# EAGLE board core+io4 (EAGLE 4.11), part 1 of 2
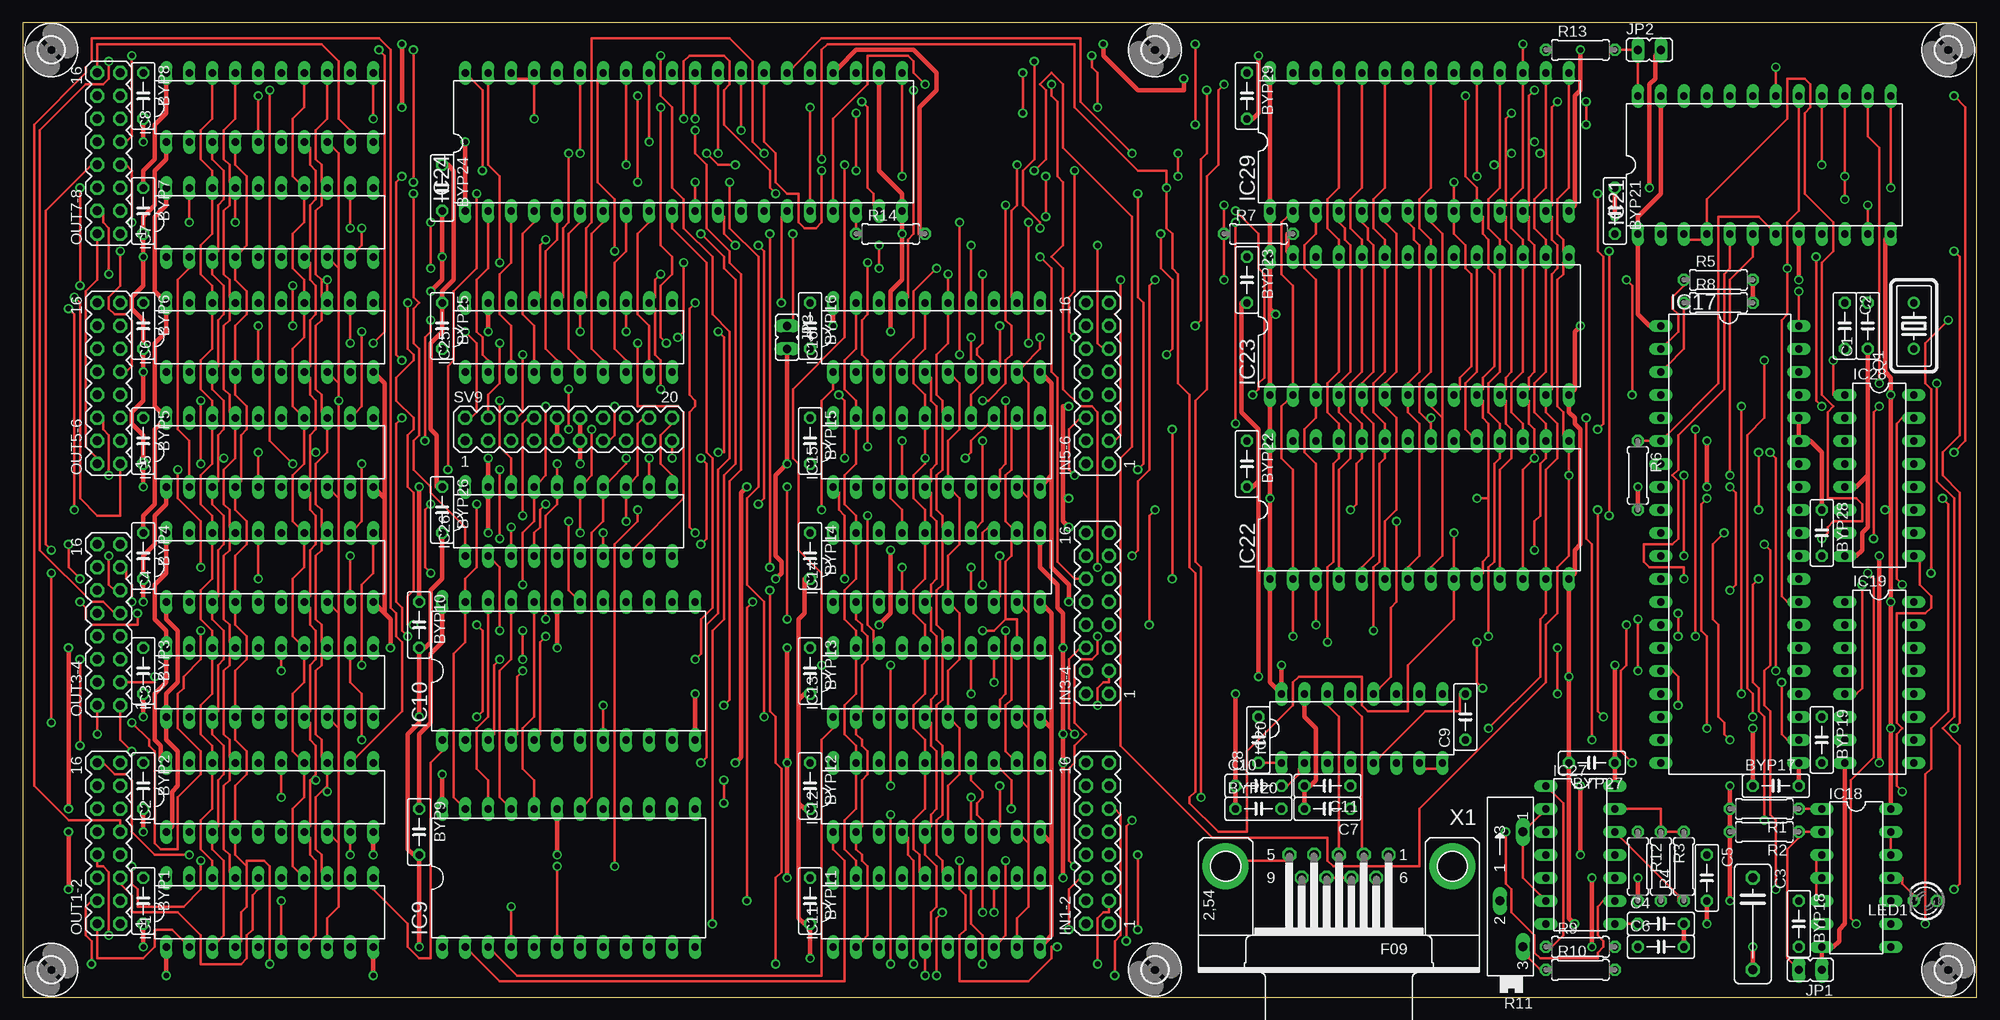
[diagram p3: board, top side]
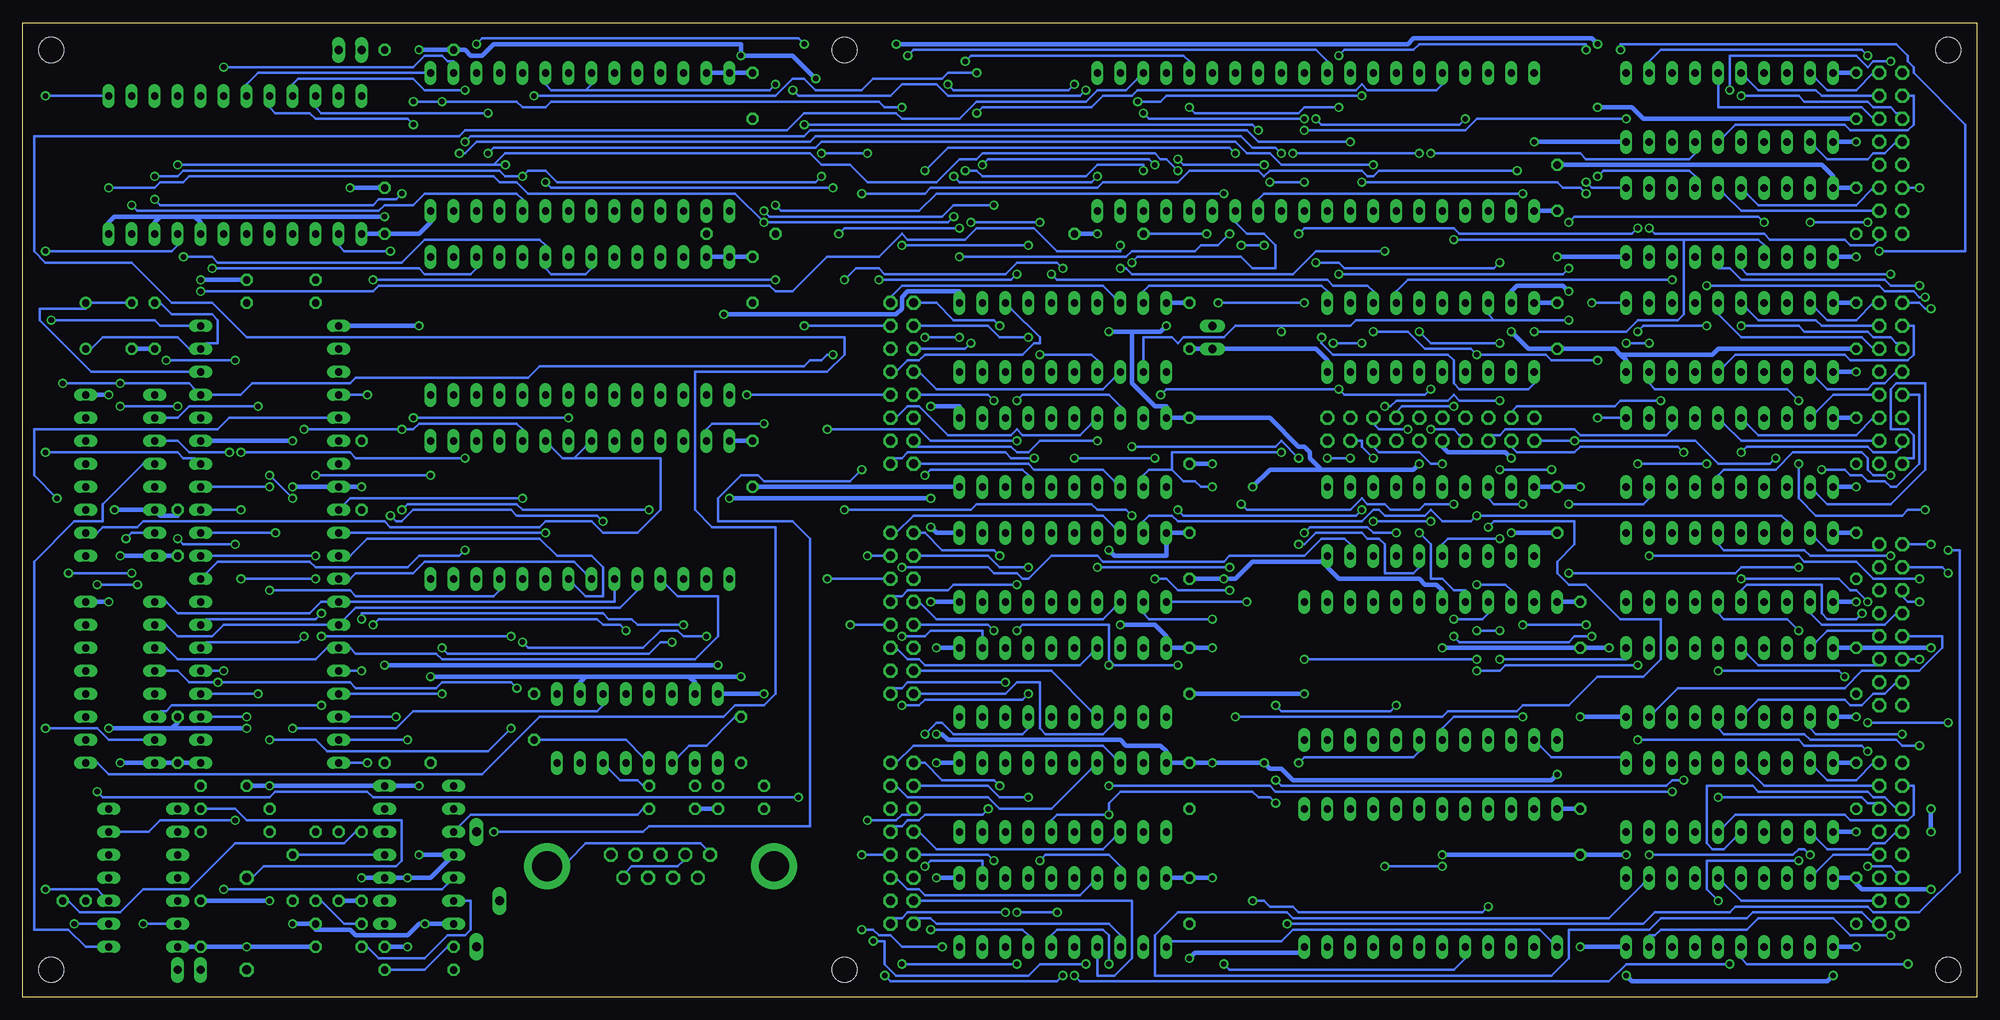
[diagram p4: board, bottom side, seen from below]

Size 215.88 x 107.62 mm. Coordinates in mm from the lower left corner, seen from the top.
Outline: 0,0 215.88,0 215.88,107.62 0,107.62 0,0
Copper layers (1*16): Top 0.035mm / dielectric 1.5mm / Bottom 0.035mm
Design rules "default": minimum track width 10mil, minimum drill 24mil, track to track 8mil, track to pad 8mil, pad to pad 8mil, via to via 8mil, smd to smd 8mil, copper to edge 40mil, drill to drill 8mil, minimum pad ring 10mil, minimum via ring 8mil, stop-mask expansion 4mil, vias tented up to drill 0mil, thermal gap 10mil
Net classes: 1 Power: width 0.508 mm, drill 0.254 mm, clearance 0.254 mm

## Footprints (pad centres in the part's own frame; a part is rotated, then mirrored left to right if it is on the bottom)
C050-025X075 = drill 0.813 octagon: 1 -2.54,0; 2 2.54,0
C102-043X133 = drill 1.016 octagon: 1 -5.08,0; 2 5.08,0
DIL20 = drill 0.813 long: 1 -11.43,-3.81; 2 -8.89,-3.81; 3 -6.35,-3.81; 4 -3.81,-3.81; 5 -1.27,-3.81; 6 1.27,-3.81; 7 3.81,-3.81; 8 6.35,-3.81; 9 8.89,-3.81; 10 11.43,-3.81; 11 11.43,3.81; 12 8.89,3.81; 13 6.35,3.81; 14 3.81,3.81; 15 1.27,3.81; 16 -1.27,3.81; 17 -3.81,3.81; 18 -6.35,3.81; 19 -8.89,3.81; 20 -11.43,3.81
DIL24-6 = drill 0.813 long: 1 -13.97,-7.62; 2 -11.43,-7.62; 3 -8.89,-7.62; 4 -6.35,-7.62; 5 -3.81,-7.62; 6 -1.27,-7.62; 7 1.27,-7.62; 8 3.81,-7.62; 9 6.35,-7.62; 10 8.89,-7.62; 11 11.43,-7.62; 12 13.97,-7.62; 13 13.97,7.62; 14 11.43,7.62; 15 8.89,7.62; 16 6.35,7.62; 17 3.81,7.62; 18 1.27,7.62; 19 -1.27,7.62; 20 -3.81,7.62; 21 -6.35,7.62; 22 -8.89,7.62; 23 -11.43,7.62; 24 -13.97,7.62
DIL40 = drill 0.813 long: 1 -24.13,-7.62; 2 -21.59,-7.62; 3 -19.05,-7.62; 4 -16.51,-7.62; 5 -13.97,-7.62; 6 -11.43,-7.62; 7 -8.89,-7.62; 8 -6.35,-7.62; 9 -3.81,-7.62; 10 -1.27,-7.62; 11 1.27,-7.62; 12 3.81,-7.62; 13 6.35,-7.62; 14 8.89,-7.62; 15 11.43,-7.62; 16 13.97,-7.62; 17 16.51,-7.62; 18 19.05,-7.62; 19 21.59,-7.62; 20 24.13,-7.62; 21 24.13,7.62; 22 21.59,7.62; 23 19.05,7.62; 24 16.51,7.62; 25 13.97,7.62; 26 11.43,7.62; 27 8.89,7.62; 28 6.35,7.62; 29 3.81,7.62; 30 1.27,7.62; 31 -1.27,7.62; 32 -3.81,7.62; 33 -6.35,7.62; 34 -8.89,7.62; 35 -11.43,7.62; 36 -13.97,7.62; 37 -16.51,7.62; 38 -19.05,7.62; 39 -21.59,7.62; 40 -24.13,7.62
DIL14 = drill 0.813 long: 1 -7.62,-3.81; 2 -5.08,-3.81; 3 -2.54,-3.81; 4 0,-3.81; 5 2.54,-3.81; 6 5.08,-3.81; 7 7.62,-3.81; 8 7.62,3.81; 9 5.08,3.81; 10 2.54,3.81; 11 0,3.81; 12 -2.54,3.81; 13 -5.08,3.81; 14 -7.62,3.81
DIL16 = drill 0.813 long: 1 -8.89,-3.81; 2 -6.35,-3.81; 3 -3.81,-3.81; 4 -1.27,-3.81; 5 1.27,-3.81; 6 3.81,-3.81; 7 6.35,-3.81; 8 8.89,-3.81; 9 8.89,3.81; 10 6.35,3.81; 11 3.81,3.81; 12 1.27,3.81; 13 -1.27,3.81; 14 -3.81,3.81; 15 -6.35,3.81; 16 -8.89,3.81
DIL24 = drill 0.813 long: 1 -13.97,-7.62; 2 -11.43,-7.62; 3 -8.89,-7.62; 4 -6.35,-7.62; 5 -3.81,-7.62; 6 -1.27,-7.62; 7 1.27,-7.62; 8 3.81,-7.62; 9 6.35,-7.62; 10 8.89,-7.62; 11 11.43,-7.62; 12 13.97,-7.62; 13 13.97,7.62; 14 11.43,7.62; 15 8.89,7.62; 16 6.35,7.62; 17 3.81,7.62; 18 1.27,7.62; 19 -1.27,7.62; 20 -3.81,7.62; 21 -6.35,7.62; 22 -8.89,7.62; 23 -11.43,7.62; 24 -13.97,7.62
DIL28 = drill 0.813 long: 1 -16.51,-7.62; 2 -13.97,-7.62; 3 -11.43,-7.62; 4 -8.89,-7.62; 5 -6.35,-7.62; 6 -3.81,-7.62; 7 -1.27,-7.62; 8 1.27,-7.62; 9 3.81,-7.62; 10 6.35,-7.62; 11 8.89,-7.62; 12 11.43,-7.62; 13 13.97,-7.62; 14 16.51,-7.62; 15 16.51,7.62; 16 13.97,7.62; 17 11.43,7.62; 18 8.89,7.62; 19 6.35,7.62; 20 3.81,7.62; 21 1.27,7.62; 22 -1.27,7.62; 23 -3.81,7.62; 24 -6.35,7.62; 25 -8.89,7.62; 26 -11.43,7.62; 27 -13.97,7.62; 28 -16.51,7.62
MA08-2 = drill 1.016 octagon: 1 -8.89,-1.27; 2 -8.89,1.27; 3 -6.35,-1.27; 4 -6.35,1.27; 5 -3.81,-1.27; 6 -3.81,1.27; 7 -1.27,-1.27; 8 -1.27,1.27; 9 1.27,-1.27; 10 1.27,1.27; 11 3.81,-1.27; 12 3.81,1.27; 13 6.35,-1.27; 14 6.35,1.27; 15 8.89,-1.27; 16 8.89,1.27
JP1 = drill 0.914 long: 1 0,-1.27; 2 0,1.27
LED3MM = drill 0.813 octagon: A -1.27,0; K 1.27,0
HC18U-V = drill 0.813 round: 1 -2.54,0; 2 2.54,0
0207/7 = drill 0.813 octagon: 1 -3.81,0; 2 3.81,0
SP19L = drill 1.016 long: A 5.715,-1.27; E -6.985,-1.27; S -1.905,1.27
MA10-2 = drill 1.016 octagon: 1 -11.43,-1.27; 2 -11.43,1.27; 3 -8.89,-1.27; 4 -8.89,1.27; 5 -6.35,-1.27; 6 -6.35,1.27; 7 -3.81,-1.27; 8 -3.81,1.27; 9 -1.27,-1.27; 10 -1.27,1.27; 11 1.27,-1.27; 12 1.27,1.27; 13 3.81,-1.27; 14 3.81,1.27; 15 6.35,-1.27; 16 6.35,1.27; 17 8.89,-1.27; 18 8.89,1.27; 19 11.43,-1.27; 20 11.43,1.27
2,8 = hole 2.8: 0,0
F09HP = drill 1.016 octagon: 1 -5.486,-1.27; 2 -2.743,-1.27; 3 0,-1.27; 4 2.743,-1.27; 5 5.486,-1.27; 6 -4.115,1.27; 7 -1.372,1.27; 8 1.372,1.27; 9 4.115,1.27 | drill 3.302 pad 5.08 round: G1 -12.522,0; G2 12.522,0

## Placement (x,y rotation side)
BYP1  .01uf  [C050-025X075]  13.33,10.63 270 top
BYP2  .01uf  [C050-025X075]  13.33,23.33 270 top
BYP3  .01uf  [C050-025X075]  13.33,36.03 270 top
BYP4  .01uf  [C050-025X075]  13.33,48.73 270 top
BYP5  .01uf  [C050-025X075]  13.33,61.43 270 top
BYP6  .01uf  [C050-025X075]  13.33,74.13 270 top
BYP7  .01uf  [C050-025X075]  13.33,86.83 270 top
BYP8  .01uf  [C050-025X075]  13.33,99.53 270 top
BYP9  .01uf  [C050-025X075]  43.81,18.25 270 top
BYP10  .01uf  [C050-025X075]  43.81,41.11 270 top
BYP11  .01uf  [C050-025X075]  86.99,10.63 270 top
BYP12  .01uf  [C050-025X075]  86.99,23.33 270 top
BYP13  .01uf  [C050-025X075]  86.99,36.03 270 top
BYP14  .01uf  [C050-025X075]  86.99,48.73 270 top
BYP15  .01uf  [C050-025X075]  86.99,61.43 270 top
BYP16  .01uf  [C050-025X075]  86.99,74.13 270 top
BYP17  .01uf  [C050-025X075]  193.67,23.33 0 top
BYP18  .01uf  [C050-025X075]  196.21,8.09 270 top
BYP19  .01uf  [C050-025X075]  198.75,28.41 270 top
BYP20  .01uf  [C050-025X075]  136.52,20.79 0 top
BYP21  .01uf  [C050-025X075]  175.89,86.83 270 top
BYP22  .01uf  [C050-025X075]  135.25,58.89 270 top
BYP23  .01uf  [C050-025X075]  135.25,79.21 270 top
BYP24  .01uf  [C050-025X075]  46.35,89.37 270 top
BYP25  .01uf  [C050-025X075]  46.35,74.13 270 top
BYP26  .01uf  [C050-025X075]  46.35,53.81 270 top
BYP27  .01uf  [C050-025X075]  173.35,25.87 180 top
BYP28  .01uf  [C050-025X075]  198.75,51.27 270 top
BYP29  .01uf  [C050-025X075]  135.25,99.53 270 top
C1  27pf  [C050-025X075]  203.83,74.13 90 top
C2  27pf  [C050-025X075]  201.29,74.13 270 top
C3  22uf  [C102-043X133]  191.13,8.09 270 top
C4  0.1uf  [C050-025X075]  180.97,8.09 0 top
C5  10uf  [C050-025X075]  186.05,13.17 270 top
C6  330pf  [C050-025X075]  180.97,5.55 0 top
C7  10uf  [C050-025X075]  144.14,20.79 180 top
C8  0.1uf  [C050-025X075]  136.52,28.41 90 top
C9  0.1uf  [C050-025X075]  159.38,30.95 90 top
C10  0.1uf  [C050-025X075]  136.52,23.33 0 top
C11  0.1uf  [C050-025X075]  144.14,23.33 180 top
IC1  74LS374N  [DIL20]  27.3,9.36 0 top
IC2  74LS374N  [DIL20]  27.3,22.06 0 top
IC3  74LS374N  [DIL20]  27.3,34.76 0 top
IC4  74LS374N  [DIL20]  27.3,47.46 0 top
IC5  74LS374N  [DIL20]  27.3,60.16 0 top
IC6  74LS374N  [DIL20]  27.3,72.86 0 top
IC7  74LS374N  [DIL20]  27.3,85.56 0 top
IC8  74LS374N  [DIL20]  27.3,98.26 0 top
IC9  74154N  [DIL24-6]  60.32,13.17 0 top
IC10  74154N  [DIL24-6]  60.32,36.03 0 top
IC11  74LS373N  [DIL20]  100.96,9.36 0 top
IC12  74LS373N  [DIL20]  100.96,22.06 0 top
IC13  74LS373N  [DIL20]  100.96,34.76 0 top
IC14  74LS373N  [DIL20]  100.96,47.46 0 top
IC15  74LS373N  [DIL20]  100.96,60.16 0 top
IC16  74LS373N  [DIL20]  100.96,72.86 0 top
IC17  [DIL40]  188.59,50 270 top
IC18  74LS00N  [DIL14]  202.56,13.17 270 top
IC19  74LS138N  [DIL16]  205.1,34.76 270 top
IC20  MAX232  [DIL16]  147.95,29.68 0 top
IC21  [DIL24]  192.4,91.91 0 top
IC22  5565  [DIL28]  154.3,53.81 0 top
IC23  2764  [DIL28]  154.3,74.13 0 top
IC24  [DIL40]  73.02,94.45 0 top
IC25  74LS245N  [DIL20]  60.32,72.86 0 top
IC26  74LS245N  [DIL20]  60.32,52.54 0 top
IC27  LM556N  [DIL14]  172.08,15.71 270 top
IC28  74LS138N  [DIL16]  205.1,57.62 270 top
IC29  2764  [DIL28]  154.3,94.45 0 top
IN1-2  [MA08-2]  118.74,16.98 90 top
IN3-4  [MA08-2]  118.74,42.38 90 top
IN5-6  [MA08-2]  118.74,67.78 90 top
JP1  RESET  [JP1]  197.48,3.01 90 top
JP2  DEBUG  [JP1]  179.7,104.61 270 top
JP3  CB1  [JP1]  84.45,72.86 180 top
LED1  [LED3MM]  210.18,10.63 180 top
OUT1-2  [MA08-2]  9.52,16.98 90 top
OUT3-4  [MA08-2]  9.52,41.11 90 top
OUT5-6  [MA08-2]  9.52,67.78 90 top
OUT7-8  [MA08-2]  9.52,93.18 90 top
Q1  4Mhz  [HC18U-V]  208.91,74.13 90 top
R1  10K  [0207/7]  192.4,20.79 180 top
R2  10K  [0207/7]  192.4,18.25 180 top
R3  100K  [0207/7]  180.97,14.44 270 top
R4  100K  [0207/7]  183.51,14.44 90 top
R5  3.3K  [0207/7]  187.32,79.21 0 top
R6  3.3K  [0207/7]  178.43,57.62 270 top
R7  3.3K  [0207/7]  136.52,84.29 0 top
R8  3.3K  [0207/7]  187.32,76.67 0 top
R9  1.8K  [0207/7]  172.08,5.55 0 top
R10  10K  [0207/7]  172.08,3.01 0 top
R11  10K  [SP19L]  164.46,12.54 90 top
R12  270  [0207/7]  178.43,14.44 270 top
R13  1K  [0207/7]  172.08,104.61 0 top
R14  3.3K  [0207/7]  95.88,84.29 0 top
SV9  [MA10-2]  60.32,62.7 0 top
U$1  [2,8]  125.09,3.01 0 top
U$2  [2,8]  125.09,104.61 0 top
U$3  [2,8]  3.17,104.61 0 top
U$4  [2,8]  3.17,3.01 0 top
U$5  [2,8]  212.72,104.61 0 top
U$6  [2,8]  212.72,3.01 0 top
X1  [F09HP]  145.41,14.44 180 top

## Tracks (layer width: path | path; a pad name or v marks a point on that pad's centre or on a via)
A00  (via drill 0.61)
  Top 0.254: 161.92,55.08 161.92,63.34 161.28,63.97 161.28,65.88 IC23.10 161.28,67.14 161.28,68.41 162.56,69.69 162.56,79.84 161.92,80.48 161.92,83.66 161.28,84.29 161.28,86.19 IC29.10 160.65,88.1 160.65,89.37 159.38,90.64 v159.38,99.53 | 161.92,55.08 161.92,48.73 161.28,48.09 161.28,46.82 IC22.10 | 161.92,55.08 v160.65,55.08 | v203.83,87.47 203.83,85.56 IC21.11 | v110.48,102.07 v110.48,97.62
  Bottom 0.254: v160.65,55.08 179.7,55.08 180.34,54.45 IC17.9 | v203.83,87.47 203.19,86.83 176.53,86.83 175.89,87.47 172.72,87.47 171.44,88.73 161.28,88.73 160.65,88.1 IC29.10 | v110.48,97.62 109.85,98.26 97.78,98.26 96.52,99.53 93.34,99.53 92.7,100.16 68.57,100.16 67.94,100.8 67.3,100.16 59.69,100.16 59.05,100.8 IC24.36 | v110.48,102.07 113.66,102.07 114.3,101.44 121.91,101.44 123.19,100.16 128.27,100.16 129.53,101.44 130.81,101.44 132.71,99.53 v159.38,99.53
A01  (via drill 0.61)
  Top 0.254: IC23.9 158.75,67.14 158.75,68.41 160.01,69.69 160.01,79.84 159.38,80.48 159.38,83.02 158.11,84.29 158.11,85.56 IC29.9 158.11,88.1 v158.11,90 | v158.11,51.27 158.11,47.46 IC22.9 158.11,44.92 158.11,41.74 153.03,36.66 153.03,31.58 148.59,31.58 147.95,32.22 147.95,35.39 140.97,35.39 140.33,34.76 140.33,32.22 135.25,27.14 135.25,18.25 132.07,18.25 128.9,21.42 128.9,22.06 129.53,22.7 129.53,46.82 128.9,47.46 128.9,66.51 127.63,67.78 127.63,79.84 126.99,80.48 126.99,84.29 126.36,84.92 v126.36,89.37 126.36,91.28 123.19,91.28 116.2,98.26 116.2,105.25 88.89,105.25 88.26,104.61 v88.26,92.55 | v61.59,93.18 61.59,100.8 IC24.35 | v75.56,93.18 76.83,91.91 v78.73,91.91
  Bottom 0.254: v158.11,51.27 179.7,51.27 IC17.10 | v75.56,93.18 v61.59,93.18 | v78.73,91.91 87.62,91.91 v88.26,92.55 | v158.11,90 157.47,89.37 v126.36,89.37
A02
  Top 0.254: 156.84,63.97 156.84,48.73 155.57,47.46 IC22.8 | 156.84,63.97 155.57,65.24 IC23.8 | 156.84,63.97 156.84,84.29 155.57,85.56 IC29.8
  Bottom 0.254: IC17.11 179.7,48.73 177.79,50.63 158.75,50.63 156.84,48.73 153.03,48.73 151.76,47.46 151.76,44.28 153.66,44.28 154.94,45.55 IC22.8
A03
  Top 0.254: IC22.7 153.03,47.46 154.3,48.73 154.3,63.34 153.03,64.61 153.03,65.24 IC23.7 153.03,67.78 154.3,69.05 154.3,83.02 153.66,83.66 153.66,84.92 153.03,85.56 IC29.7
  Bottom 0.254: IC17.12 179.7,46.19 179.06,46.82 172.72,46.82 171.44,48.09 154.94,48.09 153.66,46.82 IC22.7
A04
  Top 0.254: IC29.6 150.49,85.56 151.76,84.29 151.76,69.05 150.49,67.78 IC23.6 150.49,65.24 151.76,63.97 151.76,53.81 150.49,52.54 150.49,47.46 IC22.6
  Bottom 0.254: IC22.6 150.49,44.92 150.49,43.65 179.7,43.65 IC17.13 182.24,43.65 182.88,43.65 184.14,42.38 198.75,42.38 200.02,43.65 IC19.1
A05
  Top 0.254: IC22.5 147.95,47.46 149.22,48.73 149.22,63.34 147.95,64.61 147.95,65.24 IC23.5 147.95,67.78 149.22,69.05 149.22,83.02 148.59,83.66 148.59,84.92 147.95,85.56 IC29.5
  Bottom 0.254: IC19.2 200.02,41.11 198.75,39.84 194.94,39.84 193.67,41.11 182.24,41.11 IC17.14 180.34,41.74 179.06,43.02 149.85,43.02 147.95,44.92 IC22.5
A06
  Top 0.254: IC22.4 145.41,47.46 145.41,58.25 146.68,59.52 146.68,63.34 145.41,64.61 145.41,65.24 IC23.4 145.41,67.78 146.68,69.05 146.68,83.02 146.04,83.66 146.04,84.92 145.41,85.56 IC29.4
  Bottom 0.254: IC19.3 200.02,38.57 198.75,37.3 183.51,37.3 182.24,38.57 IC17.15 179.7,38.57 179.06,37.94 170.17,37.94 169.54,37.3 141.6,37.3 139.06,39.84 139.06,44.28 143.5,44.28 144.78,45.55 IC22.4
A07  (via drill 0.61)
  Top 0.254: v182.88,32.22 182.88,35.39 182.24,36.03 IC17.16 | IC29.3 142.87,85.56 142.87,84.29 141.6,83.02 141.6,80.48 142.87,79.21 142.87,67.78 IC23.3 142.87,65.24 142.87,63.97 141.6,62.7 141.6,60.16 142.87,58.89 142.87,47.46 IC22.3 142.87,44.92 v142.87,41.11 | v178.43,41.74 v178.43,36.03
  Bottom 0.254: v182.88,32.22 199.38,32.22 200.02,31.58 200.66,31.58 IC19.6 | v178.43,36.03 179.7,36.03 IC17.16 | v178.43,41.74 178.43,42.38 151.76,42.38 151.12,41.74 148.59,41.74 147.95,41.11 v142.87,41.11
A08  (via drill 0.61)
  Top 0.254: IC29.25 145.41,100.8 145.41,89.37 144.14,88.1 144.14,84.92 145.41,83.66 145.41,83.02 IC23.25 145.41,80.48 145.41,69.05 144.14,67.78 144.14,64.61 145.41,63.34 145.41,62.7 IC22.25 145.41,60.16 145.41,59.52 144.78,58.89 144.78,48.09 144.14,47.46 v144.14,39.2 | v169.54,38.57 v169.54,33.49
  Bottom 0.254: v169.54,33.49 179.7,33.49 IC17.17 | v169.54,38.57 168.91,37.94 146.68,37.94 145.41,39.2 v144.14,39.2
A09  (via drill 0.61)
  Top 0.254: IC29.24 147.95,100.8 147.95,89.37 146.68,88.1 146.68,84.92 147.95,83.66 147.95,83.02 IC23.24 147.95,80.48 147.95,69.05 146.68,67.78 146.68,64.61 147.95,63.34 147.95,62.7 IC22.24 147.95,60.16 147.95,59.52 147.31,58.89 147.31,54.45 v146.68,53.81 | v174.62,30.95 173.98,31.58 v173.98,53.81
  Bottom 0.254: v174.62,30.95 179.7,30.95 IC17.18 | v173.98,53.81 173.35,54.45 161.28,54.45 160.65,53.81 v146.68,53.81
A10  (via drill 0.61)
  Top 0.254: 155.57,63.34 154.3,64.61 154.3,67.78 155.57,69.05 155.57,80.48 IC23.21 155.57,83.02 155.57,83.66 154.3,84.92 154.3,88.1 155.57,89.37 155.57,100.8 IC29.21 | 155.57,63.34 155.57,62.7 IC22.21 | v173.35,28.41 173.35,50 172.72,50.63 v172.72,63.97 | 155.57,63.34 v155.57,63.97
  Bottom 0.254: v173.35,28.41 179.7,28.41 IC17.19 | v155.57,63.97 v172.72,63.97
A11  (via drill 0.61)
  Top 0.254: IC29.23 150.49,100.8 150.49,89.37 149.22,88.1 149.22,84.92 150.49,83.66 150.49,83.02 IC23.23 150.49,80.48 150.49,69.05 149.22,67.78 149.22,64.61 150.49,63.34 150.49,62.7 IC22.23 150.49,60.16 150.49,59.52 149.85,58.89 149.85,48.09 149.22,47.46 v149.22,40.48 | v177.79,25.87 176.53,27.14 176.53,36.03 177.16,36.66 v177.16,41.11
  Bottom 0.254: v177.79,25.87 179.7,25.87 IC17.20 | v177.16,41.11 176.53,41.74 152.39,41.74 151.76,41.11 149.85,41.11 v149.22,40.48
A12  (via drill 0.61)
  Top 0.254: v194.31,34.76 194.31,29.04 194.94,28.41 IC17.22 | IC29.2 139.69,86.19 139.06,85.56 139.06,79.84 140.33,78.58 140.33,67.78 IC23.2 139.69,65.88 139.06,65.24 139.06,59.52 140.33,58.25 140.33,47.46 IC22.2 140.33,44.92 v140.33,39.84 | v161.28,34.12 160.65,34.76 v160.65,39.2
  Bottom 0.254: IC19.4 200.02,36.03 198.75,36.03 197.48,34.76 v194.31,34.76 179.7,34.76 179.06,34.12 170.17,34.12 169.54,34.76 161.92,34.76 v161.28,34.12 | v160.65,39.2 160.01,38.57 147.31,38.57 145.41,40.48 143.5,40.48 142.87,39.84 v140.33,39.84
A13  (via drill 0.61)
  Top 0.254: v191.13,30.95 191.13,33.49 190.5,34.12 190.5,62.06 192.4,63.97 v192.4,70.32 | v200.02,70.32 200.02,66.51 IC28.1
  Bottom 0.254: v191.13,30.95 194.94,30.95 IC17.23 | v192.4,70.32 v200.02,70.32
A14  (via drill 0.61)
  Top 0.254: v189.86,65.24 v189.86,33.49
  Bottom 0.254: v189.86,33.49 194.94,33.49 IC17.24 | v189.86,65.24 197.48,65.24 198.75,63.97 200.02,63.97 IC28.2
A15  (via drill 0.61)
  Top 0.254: v193.67,36.03 193.67,59.52 v193.03,60.16
  Bottom 0.254: v193.67,36.03 194.94,36.03 IC17.25 | v193.03,60.16 197.48,60.16 198.75,61.43 200.02,61.43 IC28.3
AB\
  Bottom 0.254: 154.94,59.52 153.66,60.8 IC22.22 | 154.94,59.52 156.2,59.52 157.47,60.8 IC22.20 | 154.94,59.52 145.41,59.52 145.41,53.81 147.95,51.27 151.76,51.27 153.03,52.54 158.11,52.54 158.75,51.91 175.25,51.91 175.89,52.54 202.56,52.54 203.19,51.91 207,51.91 207.64,51.27 IC28.10
CB1  (via drill 0.61)
  Top 0.254: IC24.18 92.07,85.56 92.07,84.92 R14.1 | v85.08,84.29 85.08,74.77 JP3.1
  Bottom 0.254: v85.08,84.29 91.44,84.29 R14.1
CD\  (via drill 0.61)
  Top 0.254: v207.64,22.7 207,23.33 207,29.04 207.64,29.68 207,30.31 207,42.38 210.18,42.38 210.81,43.02 210.81,44.28 209.54,45.55 209.54,48.09 IC28.9 | v130.17,22.06 130.17,47.46 129.53,48.09 129.53,65.88 130.81,67.14 130.81,90.64 132.07,91.91 132.07,100.16 v132.71,100.8
  Bottom 0.254: 153.66,100.16 157.47,100.16 158.11,100.8 IC29.20 | 153.66,100.16 153.03,100.8 IC29.22 | v207.64,22.7 207,22.06 188.59,22.06 187.95,22.7 177.79,22.7 177.16,22.06 v130.17,22.06 | v132.71,100.8 133.34,100.16 153.66,100.16
D0  (via drill 0.61)
  Top 0.254: IC22.11 163.19,47.46 163.19,58.25 164.46,59.52 164.46,62.7 163.82,63.34 163.82,65.88 IC23.11 163.82,67.14 163.82,68.41 164.46,69.05 164.46,83.02 163.82,83.66 163.82,86.19 IC29.11 163.82,87.47 163.82,93.18 | v164.46,97.62 163.82,96.99 163.82,93.18 | v66.67,91.91 66.67,100.8 IC24.33 | v164.46,93.18 163.82,93.18 | v188.59,56.35 189.22,55.71 189.22,45.55 v188.59,44.92
  Bottom 0.254: v164.46,97.62 182.88,97.62 183.51,98.26 IC21.22 | v66.67,91.91 76.83,91.91 78.1,93.18 80.64,93.18 81.91,94.45 127.63,94.45 128.27,93.81 163.82,93.81 v164.46,93.18 | v188.59,56.35 194.94,56.35 IC17.33 | v188.59,44.92 179.7,44.92 179.06,44.28 163.82,44.28 163.19,44.92 IC22.11
D1  (via drill 0.61)
  Top 0.254: IC22.12 165.73,47.46 165.73,58.25 v167,59.52 167,62.7 166.37,63.34 166.37,65.88 IC23.12 166.37,67.14 166.37,68.41 167,69.05 167,83.02 166.37,83.66 166.37,86.19 IC29.12 166.37,87.47 166.37,94.45 | v167,100.16 166.37,99.53 166.37,94.45 | v69.21,94.45 69.21,100.8 IC24.32 | v167,94.45 166.37,94.45 | v191.76,60.16 v191.76,53.81
  Bottom 0.254: v167,100.16 171.44,100.16 172.72,101.44 185.41,101.44 186.05,100.8 IC21.21 | v69.21,94.45 79.37,94.45 80.64,95.72 128.9,95.72 129.53,95.08 166.37,95.08 v167,94.45 | v191.76,53.81 194.94,53.81 IC17.32 | v191.76,60.16 179.7,60.16 179.06,59.52 v167,59.52
D2  (via drill 0.61)
  Top 0.254: v172.72,98.89 v172.72,96.36 | v169.54,98.89 168.91,98.26 168.91,87.47 IC29.13 168.91,86.19 168.91,83.66 169.54,83.02 169.54,80.48 168.91,79.84 168.91,67.14 IC23.13 168.27,65.24 168.27,64.61 169.54,63.34 169.54,59.52 168.27,58.25 168.27,47.46 IC22.13 168.27,44.92 168.27,42.38 167.63,41.74 167.63,35.39 v161.92,29.68 | v118.1,103.97 118.1,102.7 118.74,102.07 v118.74,98.26 | v187.95,51.27 186.69,50 186.69,41.74 187.32,41.11 187.32,30.95 187.95,30.31 187.95,29.04 v188.59,28.41
  Bottom 0.254: v172.72,96.36 173.35,96.99 183.51,96.99 184.14,97.62 187.95,97.62 188.59,98.26 IC21.20 | v172.72,98.89 v169.54,98.89 161.28,98.89 160.65,98.26 158.11,98.26 157.47,98.89 121.28,98.89 120.64,98.26 v118.74,98.26 | v118.1,103.97 117.47,104.61 73.02,104.61 71.75,103.34 IC24.31 | v187.95,51.27 194.94,51.27 IC17.31 | v188.59,28.41 183.51,28.41 182.24,27.14 164.46,27.14 v161.92,29.68
D3  (via drill 0.61)
  Top 0.254: v74.29,96.99 74.29,100.8 IC24.30 | v92.07,91.28 v92.07,97.62 | v111.75,91.28 113.02,92.55 113.02,100.16 112.39,100.8 113.66,102.07 114.93,100.8 114.93,93.81 122.55,86.19 122.55,60.8 121.28,59.52 121.28,27.77 131.44,17.61 144.14,17.61 144.14,15.08 144.78,14.44 154.3,14.44 154.3,20.79 168.27,34.76 168.27,41.11 169.54,42.38 169.54,47.46 170.81,48.73 v170.81,57.62 170.81,60.16 IC22.15 170.17,62.06 170.17,64.61 169.54,65.24 169.54,79.21 170.17,79.84 170.17,81.11 IC23.15 170.17,82.39 170.17,83.66 169.54,84.29 169.54,88.1 170.81,89.37 170.81,100.8 IC29.15 | v183.51,57.62 v183.51,48.73
  Bottom 0.254: IC29.15 171.44,102.07 189.86,102.07 191.13,100.8 IC21.19 | v74.29,96.99 91.44,96.99 v92.07,97.62 | v92.07,91.28 92.07,91.91 97.15,91.91 98.42,90.64 109.85,90.64 110.48,91.28 v111.75,91.28 | v183.51,48.73 194.94,48.73 IC17.30 | v170.81,57.62 v183.51,57.62
D4  (via drill 0.61)
  Top 0.254: 168.27,93.18 168.27,89.37 167,88.1 167,84.92 168.27,83.66 168.27,83.02 IC23.16 168.27,80.48 168.27,69.05 167,67.78 167,64.61 168.27,63.34 168.27,62.7 IC22.16 168.27,60.16 168.27,59.52 167.63,58.89 167.63,53.17 167,52.54 v167,49.37 | 168.27,93.18 168.27,100.8 IC29.16 | v193.67,102.7 193.67,100.8 IC21.18 | v76.83,93.18 76.83,100.8 IC24.29 | v167.63,93.18 168.27,93.18
  Bottom 0.254: v193.67,102.7 172.72,102.7 171.44,103.97 169.54,103.97 168.91,103.34 168.27,103.34 IC29.16 | v76.83,93.18 77.46,93.81 80,93.81 81.27,95.08 128.27,95.08 128.9,94.45 165.73,94.45 167,93.18 v167.63,93.18 | v167,49.37 167.63,48.73 172.08,48.73 173.35,47.46 183.51,47.46 184.14,48.09 194.31,48.09 195.57,46.82 IC17.29
D5  (via drill 0.61)
  Top 0.254: IC21.17 196.21,98.26 196.21,86.83 194.94,85.56 v194.94,80.48 194.94,75.4 194.31,74.77 194.31,44.28 194.94,43.65 IC17.28 | IC22.17 165.73,62.7 165.73,63.34 164.46,64.61 164.46,67.78 165.73,69.05 165.73,80.48 IC23.17 165.73,83.02 165.73,83.66 164.46,84.92 164.46,88.1 165.73,89.37 165.73,100.8 IC29.17 165.73,103.34 v165.73,105.25 | v79.37,95.72 79.37,100.8 IC24.28 | v129.53,105.25 v129.53,96.36
  Bottom 0.254: v79.37,95.72 80,96.36 v129.53,96.36 | v129.53,105.25 130.17,105.88 165.09,105.88 v165.73,105.25 | v194.94,80.48 172.08,80.48 171.44,79.84 166.37,79.84 165.73,80.48 IC23.17
D6  (via drill 0.61)
  Top 0.254: 163.19,91.91 163.19,89.37 161.92,88.1 161.92,84.92 163.19,83.66 163.19,83.02 IC23.18 163.19,80.48 163.19,69.05 161.92,67.78 161.92,64.61 163.19,63.34 163.19,62.7 IC22.18 163.19,60.16 163.19,59.52 162.56,58.89 162.56,48.09 161.92,47.46 v161.92,39.84 | 163.19,91.91 163.19,100.8 IC29.18 | v182.88,39.84 v182.88,42.38 | v198.75,91.91 198.75,98.26 IC21.16 | v162.56,91.91 163.19,91.91 | v88.26,91.28 88.26,85.56 87.62,84.92 86.35,84.92 85.72,85.56 85.72,88.73 84.45,88.73 83.18,90 83.18,93.18 81.91,94.45 81.91,100.8 IC24.27
  Bottom 0.254: v182.88,42.38 183.51,41.74 195.57,41.74 IC17.27 | v161.92,39.84 v182.88,39.84 | 163.82,91.91 v162.56,91.91 | 163.82,91.91 v198.75,91.91 | v88.26,91.28 89.53,92.55 90.16,92.55 90.8,93.18 109.85,93.18 110.48,92.55 112.39,92.55 114.93,90 122.55,90 124.45,91.91 127.63,91.91 128.9,93.18 162.56,93.18 163.82,91.91
D7  (via drill 0.61)
  Top 0.254: IC22.19 160.01,62.06 159.38,62.7 159.38,67.78 160.65,69.05 160.65,80.48 IC23.19 | v184.78,62.7 v184.78,39.84 | v160.65,90.64 160.65,100.8 IC29.19 | IC21.15 201.29,98.26 v201.29,90.64 v201.29,88.1 | v122.55,93.18 116.83,98.89 116.83,105.88 88.26,105.88 85.08,102.7 IC24.26 | v127.63,90.64 v127.63,93.18 | v173.98,62.7 174.62,63.34 174.62,81.75 173.98,82.39 v173.98,88.73
  Bottom 0.254: v184.78,39.84 185.41,39.2 195.57,39.2 IC17.26 | v184.78,62.7 v173.98,62.7 172.72,62.7 172.08,63.34 161.28,63.34 160.65,62.7 IC22.19 | v201.29,90.64 198.75,90.64 198.12,91.28 163.19,91.28 162.56,90.64 v160.65,90.64 160.01,91.28 158.11,91.28 156.84,90 128.27,90 v127.63,90.64 | v127.63,93.18 v122.55,93.18 | v173.98,88.73 174.62,88.1 176.53,88.1 177.16,87.47 200.66,87.47 v201.29,88.1
E  (via drill 0.61)
  Top 0.254: v205.1,67.78 205.1,93.81 203.83,95.08 203.83,98.26 IC21.14 | v111.75,103.34 111.75,92.55 110.48,91.28 110.48,87.47 112.39,85.56 v112.39,84.92 | v125.72,84.29 125.72,80.48 126.99,79.21 126.99,71.59 v126.36,70.95 | v213.35,11.9 213.99,12.54 213.99,27.77 212.09,29.68 213.35,30.95 213.35,55.08 211.45,56.98 v211.45,67.78
  Bottom 0.254: v111.75,103.34 111.12,103.97 87.62,103.97 86.99,103.34 IC24.25 | v112.39,84.92 125.09,84.92 v125.72,84.29 | v126.36,70.95 126.99,70.95 127.63,70.32 128.9,70.32 129.53,69.69 158.75,69.69 160.01,68.41 179.06,68.41 179.7,67.78 190.5,67.78 191.76,66.51 194.94,66.51 IC17.37 196.84,67.14 197.48,67.78 v205.1,67.78 v211.45,67.78 | v213.35,11.9 207.64,11.9 207,11.27 IC18.10
EF\  (via drill 0.61)
  Top 0.254: v204.47,50.63 204.47,64.61 v205.1,65.24 | v198.75,65.24 198.12,65.88 v198.12,81.75
  Bottom 0.254: IC23.22 153.03,80.48 153.66,79.84 157.47,79.84 158.11,80.48 IC23.20 158.11,83.02 158.75,83.66 171.44,83.66 173.98,81.11 194.31,81.11 194.94,81.75 v198.12,81.75 | v204.47,50.63 203.83,51.27 202.56,51.27 IC28.7 | v205.1,65.24 v198.75,65.24
GND  (via drill 0.61)
  Top 0.508: JP3.2 84.45,70.95 v84.45,58.89 83.18,57.62 83.18,48.73 83.81,48.09 83.81,46.82 v83.18,46.19 | v86.99,4.28 86.99,7.46 BYP11.2 86.35,8.09 85.72,8.73 85.72,21.42 | 85.72,21.42 86.35,20.79 BYP12.2 | 85.72,32.85 85.72,21.42 | 85.72,32.85 86.35,33.49 BYP13.2 | v74.29,33.49 74.29,29.68 IC10.12 | 85.72,32.85 85.72,41.74 86.35,42.38 86.35,46.19 BYP14.2 | v13.33,5.55 13.33,7.46 BYP1.2 | v43.81,5.55 43.81,15.08 BYP9.2 43.18,15.71 42.54,16.34 42.54,29.04 43.81,30.31 v43.81,30.95 43.81,37.94 BYP10.2 44.45,38.57 45.08,39.2 45.08,44.92 46.35,46.19 46.35,50.63 BYP26.2 | v38.73,15.71 38.73,16.98 IC2.10 | v59.05,15.71 59.05,19.52 IC9.19 | v15.87,2.38 15.87,4.28 IC1.1 | v38.73,2.38 38.73,4.28 IC1.10 | v13.33,18.25 13.33,20.15 BYP2.2 | v13.33,30.95 13.33,32.85 BYP3.2 | IC2.1 16.5,18.88 16.5,22.7 17.14,23.33 17.14,27.14 15.87,28.41 15.87,29.68 IC3.1 15.87,32.22 15.87,33.49 17.14,34.76 17.14,40.48 15.87,41.74 15.87,42.38 IC4.1 | v13.33,43.65 13.33,45.55 BYP4.2 13.33,46.82 13.33,48.73 14.6,50 14.6,53.17 15.87,54.45 15.87,55.08 IC5.1 | v13.33,56.35 13.33,58.25 BYP5.2 13.33,59.52 13.33,62.06 12.06,63.34 12.06,64.61 13.33,65.88 v13.33,69.05 13.33,70.95 BYP6.2 13.33,72.22 13.33,74.77 12.06,76.03 12.06,77.3 13.33,78.58 v13.33,81.75 13.33,83.66 BYP7.2 13.33,84.92 13.33,86.19 14.6,87.47 14.6,91.28 15.87,92.55 15.87,93.18 IC8.1 | v13.33,94.45 13.33,96.36 BYP8.2 | SV9.9 59.05,62.06 59.05,63.34 SV9.10 | v51.43,51.27 51.43,55.08 IC26.19 51.43,57.62 v51.43,59.52 | BYP24.2 46.35,86.19 v46.35,81.75 46.35,79.21 v45.08,77.94 | v48.89,94.45 48.89,88.1 IC24.1 | v51.43,73.5 51.43,75.4 IC25.19
  Top 0.508: 40,42.38 40.64,41.74 v40.64,38.57 | 40,42.38 39.37,43.02 IC4.10 | v59.05,38.57 59.05,42.38 IC10.19 | 40,55.08 39.37,55.71 IC5.10 | 40,55.08 40,42.38 | 40,55.08 40,67.78 39.37,68.41 IC6.10 | 113.66,16.98 113.66,6.82 113.02,6.18 IC11.10 | 113.66,16.98 113.02,17.61 IC12.10 | 113.66,29.68 113.02,30.31 IC13.10 | 113.66,29.68 113.66,16.98 | 113.66,29.68 113.66,42.38 113.02,43.02 IC14.10 | 113.66,57.62 113.02,56.98 IC15.10 | 113.66,57.62 113.66,67.78 113.02,68.41 IC16.10 | 136.52,56.98 136.52,62.7 134.62,64.61 134.62,76.67 BYP23.2 | 136.52,56.98 135.88,56.35 BYP22.2 | v115.56,43.65 115.56,45.55 113.66,47.46 113.66,57.62 | C6.2 183.51,6.18 183.51,7.46 C4.2 | v186.05,8.09 186.05,10 C5.2 | JP1.1 198.75,4.28 198.75,4.92 IC18.7 200.02,5.55 200.66,6.18 200.66,7.46 201.29,8.09 201.29,25.23 IC19.8 | v191.13,5.55 191.13,3.64 C3.2 | BYP17.2 196.21,23.96 196.21,25.23 IC17.21 | 203.83,57.62 202.56,56.35 IC28.5 | 203.83,57.62 203.83,70.95 C1.1 | 203.83,57.62 203.83,51.91 203.19,51.27 203.19,49.37 202.56,48.73 IC28.8 | v205.1,25.87 v205.1,48.73 | C7.2 141.6,21.42 141.6,22.7 C11.2 142.23,23.33 142.87,23.96 142.87,29.68 141.6,30.95 141.6,32.22 IC20.15 | v171.44,8.09 170.81,8.73 170.81,25.23 BYP27.2 170.81,26.5 v170.81,35.39 170.81,44.92 IC22.14 171.44,46.82 171.44,49.37 172.08,50 172.08,62.7 171.44,63.34 171.44,63.97 170.81,64.61 170.81,65.24 IC23.14 171.44,67.14 171.44,73.5 v172.08,74.13 | v136.52,103.97 136.52,97.62 135.88,96.99 BYP29.2 | IC21.23 180.97,98.26 180.97,88.73 178.43,86.19 178.43,85.56 IC21.1 178.43,83.02 178.43,75.4 179.7,74.13 IC17.1 | v172.08,104.61 172.08,100.16 171.44,99.53 171.44,87.47 IC29.14
  Top 0.508: v136.52,35.39 136.52,56.98 | v41.91,105.25 v41.91,98.26 | v119.38,105.25 119.38,103.97 123.19,100.16 128.27,100.16 v128.27,101.44
  Bottom 0.508: v84.45,58.89 86.35,58.89 BYP15.2 | IC25.10 71.75,70.32 73.02,71.59 83.18,71.59 JP3.2 85.72,71.59 86.35,71.59 BYP16.2 | v86.99,4.28 86.35,4.92 74.92,4.92 IC9.12 | v74.29,33.49 86.35,33.49 BYP13.2 | BYP14.2 86.35,46.19 v83.18,46.19 81.91,46.19 80,48.09 72.38,48.09 IC26.10 71.75,47.46 70.48,46.19 61.59,46.19 60.96,45.55 59.69,45.55 59.05,44.92 IC10.19 | v13.33,5.55 15.24,5.55 IC1.1 | v43.81,5.55 39.37,5.55 IC1.10 | v38.73,15.71 43.18,15.71 BYP9.2 44.45,15.71 v59.05,15.71 | v15.87,2.38 16.5,1.74 38.1,1.74 v38.73,2.38 | v13.33,18.25 15.24,18.25 IC2.1 | v13.33,30.95 15.24,30.95 IC3.1 | v13.33,43.65 15.24,43.65 IC4.1 | v13.33,56.35 15.24,56.35 IC5.1 | v13.33,94.45 15.24,94.45 IC8.1 | v13.33,69.05 15.24,69.05 IC6.1 | v13.33,81.75 15.24,81.75 IC7.1 | v51.43,51.27 46.98,51.27 BYP26.2 | v51.43,59.52 52.07,60.16 58.41,60.16 59.05,60.8 SV9.9 | v46.35,81.75 39.37,81.75 IC7.10 | IC24.1 48.26,86.83 46.98,86.83 BYP24.2 | v48.89,94.45 39.37,94.45 IC8.10 | 39.37,70.95 40,71.59 45.72,71.59 BYP25.2 46.98,71.59 49.53,71.59 v51.43,73.5 | 39.37,70.95 38.73,70.32 IC6.10 | v43.81,30.95 39.37,30.95 IC3.10 | v40.64,38.57 43.18,38.57 BYP10.2 44.45,38.57 v59.05,38.57 | v45.08,77.94 45.72,78.58 50.8,78.58 51.43,77.94 IC25.19 | 39.37,70.95 29.2,70.95 28.57,71.59 13.97,71.59 BYP6.2 | BYP22.2 134.62,56.35 113.02,56.35 IC15.10 | v115.56,43.65 113.02,43.65 IC14.10 | v186.05,8.09 184.14,8.09 C4.2 183.51,7.46 179.7,7.46 179.06,6.82 173.35,6.82 172.08,8.09 v171.44,8.09 169.54,8.09 IC27.7 | IC18.7 197.48,5.55 196.84,5.55 BYP18.2 195.57,5.55 v191.13,5.55 184.14,5.55 C6.2 | IC17.21 197.48,25.87 198.12,25.87 BYP19.2 199.38,25.87 200.02,25.87 IC19.8 202.56,25.87 v205.1,25.87
  Bottom 0.508: BYP28.2 199.38,48.73 200.02,48.73 IC28.8 202.56,48.73 v205.1,48.73 | C2.2 201.92,71.59 203.19,71.59 C1.1 | BYP20.2 139.69,20.79 140.97,20.79 C7.2 | 142.23,35.39 141.6,34.76 IC20.15 | 153.66,35.39 142.23,35.39 | 153.66,35.39 154.3,34.76 IC20.10 | v170.81,35.39 153.66,35.39 | v172.08,74.13 179.7,74.13 IC17.1 | IC21.1 177.79,84.29 176.53,84.29 BYP21.2 175.25,84.29 172.08,84.29 170.81,85.56 IC29.14 | v172.08,104.61 168.91,104.61 R13.1 167.63,104.61 167,104.61 166.37,103.97 165.09,103.97 163.82,105.25 136.52,105.25 v136.52,103.97 130.81,103.97 v128.27,101.44 | 142.23,35.39 v136.52,35.39 | v41.91,98.26 38.1,98.26 36.83,96.99 13.97,96.99 BYP8.2 | v41.91,105.25 42.54,105.88 62.23,105.88 62.86,105.25 v119.38,105.25
HLT\
  Top 0.254: IC17.2 181.6,72.22 182.88,73.5 182.88,75.4 182.24,76.03 182.24,77.3 183.51,78.58 R5.1
IN00
  Bottom 0.254: IC9.1 46.98,6.18 48.26,7.46 75.56,7.46 76.83,6.18 88.89,6.18 IC11.1
IN01
  Top 0.254: IC9.2 49.53,4.92 52.7,1.74 90.8,1.74 90.8,15.08 89.53,16.34 89.53,16.98 IC12.1
IN02
  Top 0.254: IC9.3 52.07,4.92 54.61,2.38 88.26,2.38 88.26,28.41 89.53,29.68 IC13.1
IN03  (via drill 0.61)
  Top 0.254: v53.97,10 53.97,6.82 IC9.4 | v80,10.63 80,43.02 v80.64,43.65
  Bottom 0.254: v53.97,10 54.61,9.36 74.92,9.36 75.56,10 78.1,10 78.73,10.63 v80,10.63 | v80.64,43.65 88.89,43.65 IC14.1
IN04  (via drill 0.61)
  Top 0.254: v83.18,3.64 83.18,13.17 83.81,13.81 83.81,25.23 83.18,25.87 83.18,30.95 82.55,31.58 v82.55,44.92 | v90.8,46.19 90.8,53.17 90.16,53.81 90.16,55.71 IC15.1
  Bottom 0.254: v83.18,3.64 82.55,3.01 57.78,3.01 56.51,4.28 IC9.5 | v82.55,44.92 88.26,44.92 89.53,46.19 v90.8,46.19
IN05  (via drill 0.61)
  Top 0.254: v59.05,14.44 59.05,6.82 IC9.6 | v65.4,14.44 65.4,50 67.94,52.54 v67.94,53.81 | v88.26,53.81 88.26,65.88 89.53,67.14 89.53,67.78 IC16.1
  Bottom 0.254: v59.05,14.44 v65.4,14.44 | v67.94,53.81 68.57,53.17 87.62,53.17 v88.26,53.81
IO-E\
  Bottom 0.254: IC19.9 207.64,25.87 206.37,24.6 165.09,24.6 158.75,30.95 138.42,30.95 137.16,32.22 133.98,32.22 132.71,33.49 132.71,51.91 139.69,51.91 141.6,53.81 141.6,69.05 126.99,69.05 125.09,70.95 125.09,72.86 191.13,72.86 194.94,76.67 199.38,76.67 203.83,81.11 213.35,81.11 214.62,82.39 214.62,95.08 167.63,95.08 167,95.72 131.44,95.72 129.53,97.62 119.38,97.62 118.74,96.99 112.39,96.99 110.48,98.89 98.42,98.89 97.15,100.16 93.97,100.16 92.7,101.44 IC24.23
IO-F\  (via drill 0.61)
  Top 0.254: v213.35,82.39 213.99,81.75 213.99,62.06 212.09,60.16 212.09,57.62 213.99,55.71 213.99,30.31 v213.35,29.68
  Bottom 0.254: v213.35,82.39 199.38,82.39 198.75,83.02 IC21.9 | v213.35,29.68 207.64,29.68 206.37,28.41 202.56,28.41 IC19.7
IRQ\  (via drill 0.61)
  Top 0.254: IC24.38 54.61,101.44 55.88,101.44 IC24.37 56.51,100.8 v56.51,96.99 | v132.71,79.21 132.71,83.66 R7.1 132.71,84.92 v132.71,87.47 | v177.16,79.21 177.79,78.58 v177.79,66.51 | v73.02,96.99 73.02,103.34 73.66,103.97 77.46,103.97 78.1,103.34 78.1,100.8 77.46,100.16 77.46,96.36 82.55,91.28 82.55,89.37 v83.18,88.73
  Bottom 0.254: v177.16,79.21 v132.71,79.21 | v177.79,66.51 179.7,66.51 IC17.4 | v56.51,96.99 57.15,96.36 72.38,96.36 v73.02,96.99 | v83.18,88.73 114.93,88.73 116.83,86.83 132.07,86.83 v132.71,87.47
MR
  Top 0.254: IC17.3 181.6,69.69 183.51,71.59 183.51,76.03 R8.1
N$1
  Bottom 0.254: IC12.3 95.24,17.61 96.52,16.34 114.93,16.34 116.83,18.25 IN1-2.10
N$2  (via drill 0.61)
  Top 0.254: v98.42,3.64 98.42,15.08 97.78,15.71 97.78,17.61 IC12.4 | v121.91,6.18 121.91,18.88 v122.55,19.52
  Bottom 0.254: v98.42,3.64 103.5,3.64 104.77,2.38 119.38,2.38 120.64,3.64 120.64,6.18 v121.91,6.18 | v122.55,19.52 119.38,19.52 118.74,20.15 117.47,20.15 IN1-2.12
N$3
  Bottom 0.254: Q1.1 208.28,71.59 207,72.86 198.75,72.86 197.48,71.59 IC17.39 195.57,72.22 194.31,72.22 194.31,74.77 194.94,75.4 199.38,75.4 200.66,76.67 C2.1
N$4
  Bottom 0.254: IC17.38 197.48,69.05 208.28,69.05 213.99,74.77 213.99,76.03 208.91,76.03 Q1.2 208.28,76.67 204.47,76.67 C1.2
N$5
  Top 0.254: IC25.2 51.43,70.32 50.8,70.95 50.8,72.86 50.16,73.5 50.16,79.21 51.43,80.48 51.43,85.56 IC24.2
N$6
  Top 0.254: IC18.5 198.12,11.27 198.12,12.54 IC18.4 198.12,13.81 198.12,15.08 IC18.3
N$7  (via drill 0.61)
  Top 0.254: v104.77,22.06 104.77,19.52 IC12.7
  Bottom 0.254: v104.77,22.06 107.94,22.06 109.21,23.33 116.83,23.33 IN1-2.14
N$8  (via drill 0.61)
  Top 0.254: v107.94,23.33 107.94,18.88 IC12.8
  Bottom 0.254: v107.94,23.33 108.58,23.96 114.3,23.96 116.2,25.87 116.83,25.87 IN1-2.16
N$9  (via drill 0.61)
  Top 0.254: v108.58,15.08 108.58,6.82 107.94,6.18 IC11.8
  Bottom 0.254: v108.58,15.08 109.21,15.71 116.83,15.71 IN1-2.8
N$10  (via drill 0.61)
  Top 0.254: v115.56,7.46 115.56,11.9 116.83,13.17 IN1-2.6
  Bottom 0.254: v115.56,7.46 105.41,7.46 104.77,6.82 IC11.7
N$11
  Bottom 0.254: IC11.4 97.15,4.28 97.15,2.38 95.24,2.38 93.34,4.28 93.34,10.63 116.83,10.63 IN1-2.4
N$12
  Bottom 0.254: IC11.3 94.61,6.82 95.88,8.09 114.93,8.09 115.56,8.73 117.47,8.73 IN1-2.2
N$13  (via drill 0.61)
  Top 0.254: v107.31,9.36 107.31,11.9 IC11.13
  Bottom 0.254: v107.31,9.36 118.1,9.36 118.74,8.73 120.01,8.73 IN1-2.1
N$14  (via drill 0.61)
  Top 0.254: v106.04,3.64 106.04,6.82 104.77,8.09 104.77,11.9 IC11.14 | v118.74,3.64 118.74,8.73 119.38,9.36 120.01,9.36 120.01,10 IN1-2.3
  Bottom 0.254: v106.04,3.64 v118.74,3.64
N$15
  Bottom 0.254: IC11.17 97.78,12.54 99.05,11.27 116.2,11.27 116.83,11.9 118.1,11.9 119.38,13.17 IN1-2.5
N$16  (via drill 0.61)
  Top 0.254: v123.19,7.46 v123.19,15.71 | v114.3,5.55 113.66,5.55 113.66,4.28 111.12,1.74 103.5,1.74 103.5,6.82 104.13,7.46 104.13,11.27 103.5,11.9 v103.5,15.08
  Bottom 0.254: v123.19,15.71 120.64,15.71 IN1-2.7 | v123.19,7.46 121.91,7.46 121.28,6.82 120.01,6.82 118.74,5.55 v114.3,5.55 | v103.5,15.08 102.86,15.71 95.88,15.71 94.61,14.44 IC11.18
N$17  (via drill 0.61)
  Top 0.254: v109.21,20.79 109.21,23.96 107.94,25.23 IC12.13
  Bottom 0.254: v109.21,20.79 109.85,20.15 116.2,20.15 116.83,19.52 118.1,19.52 118.74,18.88 120.01,18.88 IN1-2.9
N$18  (via drill 0.61)
  Top 0.254: v120.64,2.38 120.64,6.18 121.28,6.82 121.28,20.15 120.64,20.79 IN1-2.11 | v100.96,2.38 100.96,8.73 v101.59,9.36 | v106.04,9.36 106.04,19.52 105.41,20.15 105.41,21.42 106.04,22.06 106.04,22.7 104.77,23.96 104.77,24.6 IC12.14
  Bottom 0.254: v120.64,2.38 120.01,1.74 101.59,1.74 v100.96,2.38 | v101.59,9.36 v106.04,9.36
N$19
  Bottom 0.254: IC12.17 97.78,25.23 102.23,20.79 107.94,20.79 109.21,22.06 118.1,22.06 119.38,23.33 IN1-2.13
N$20
  Bottom 0.254: IC12.18 95.24,26.5 96.52,27.77 117.47,27.77 119.38,25.87 IN1-2.15
N$21
  Top 0.254: R1.1 196.84,20.79 197.48,20.79 IC18.1
  Bottom 0.254: C3.1 190.5,13.17 189.22,14.44 174.62,14.44 173.98,15.08 173.98,19.52 191.13,19.52 192.4,20.79 195.57,20.79 R1.1
N$22
  Top 0.254: IC18.2 197.48,18.25 196.84,18.25 R2.1 196.21,17.61 194.94,16.34 194.94,4.28 195.57,3.64 JP1.2
N$23  (via drill 0.61)
  Top 0.254: IC21.3 184.14,83.66 185.41,83.66 IC21.4 186.05,85.56 186.05,88.1 194.94,96.99 194.94,101.44 196.84,101.44 197.48,100.8 197.48,98.26 196.84,97.62 196.84,88.73 200.02,85.56 200.02,82.39 198.75,81.11 198.75,66.51 200.02,65.24 199.38,64.61 199.38,55.08 202.56,55.08 203.19,54.45 203.19,52.54 200.02,52.54 199.38,51.91 199.38,51.27 v198.75,50.63 | v193.67,11.9 193.67,19.52 193.03,20.15 193.03,31.58 192.4,32.22 192.4,36.03 193.03,36.66 193.03,49.37 v192.4,50
  Bottom 0.254: v193.67,11.9 169.54,11.9 168.91,12.54 IC27.5 | v192.4,50 198.12,50 v198.75,50.63
N$24  (via drill 0.61)
  Top 0.254: v52.7,40.48 52.7,47.46 52.07,48.09 IC26.2 | v55.24,37.3 v55.24,40.48 | v74.29,37.3 74.92,37.94 74.92,41.74 76.19,43.02 76.19,59.52 75.56,60.16 75.56,81.11 71.75,84.92 71.75,85.56 IC24.10
  Bottom 0.254: v55.24,40.48 v52.7,40.48 | v55.24,37.3 v74.29,37.3
N$25  (via drill 0.61)
  Top 0.254: v74.29,90 74.29,88.1 IC24.11 | v78.1,90 78.1,84.92 81.27,81.75 81.27,56.35 80,55.08 80,45.55 81.91,43.65 v81.91,30.95 | v53.97,51.91 53.97,50 IC26.3
  Bottom 0.254: v78.1,90 v74.29,90 | v81.91,30.95 59.05,30.95 58.41,31.58 50.8,31.58 50.16,32.22 45.08,32.22 41.91,35.39 36.83,35.39 34.92,37.3 34.92,41.74 39.37,41.74 43.18,45.55 45.08,45.55 46.35,46.82 46.35,48.09 44.45,50 44.45,52.54 53.34,52.54 v53.97,51.91
N$26
  Top 0.254: IC5.2 18.41,57.62 18.41,61.43 17.14,62.7 17.14,79.21 18.41,80.48 IC7.2 | OUT5-6.2 8.25,59.52 6.98,60.8 6.98,77.94 8.25,79.21 8.25,83.66 OUT7-8.2
  Bottom 0.254: IC5.2 17.77,55.71 16.5,54.45 9.52,54.45 5.71,58.25 5.71,67.78 8.89,67.78 9.52,67.14 9.52,62.7 7.62,62.7 6.98,62.06 6.98,59.52 8.25,59.52 OUT5-6.2
N$27
  Top 0.254: IC27.6 167.63,11.27 165.73,13.17 165.73,16.98 R11.A 166.37,18.88 167.63,20.15 IC27.2
  Bottom 0.254: C6.1 177.79,5.55 176.53,4.28 171.44,4.28 168.91,6.82 167,6.82 166.37,7.46 166.37,10.63 167,10.63 IC27.6
N$28
  Top 0.254: IC27.1 168.91,22.7 170.17,21.42 170.17,6.82 168.91,5.55 R9.1
  Bottom 0.254: R9.1 168.91,5.55 171.44,3.01 175.25,3.01 R10.2
N$29
  Bottom 0.254: IC14.3 95.24,43.02 96.52,41.74 114.93,41.74 116.83,43.65 IN3-4.10
N$30  (via drill 0.61)
  Top 0.254: v112.39,81.75 113.66,80.48 113.66,69.05 114.3,68.41 114.3,48.09 116.2,46.19 116.83,46.19 IN3-4.12 | v82.55,47.46 v82.55,84.29 | v97.15,47.46 97.15,44.92 IC14.4
  Bottom 0.254: v112.39,81.75 93.97,81.75 93.34,82.39 86.35,82.39 85.72,83.02 83.81,83.02 v82.55,84.29 | v82.55,47.46 v97.15,47.46
N$31  (via drill 0.61)
  Top 0.254: v104.77,47.46 104.77,44.92 IC14.7
  Bottom 0.254: v104.77,47.46 107.94,47.46 109.21,48.73 116.83,48.73 IN3-4.14
N$32  (via drill 0.61)
  Top 0.254: v107.94,48.73 107.94,44.28 IC14.8
  Bottom 0.254: v107.94,48.73 108.58,49.37 114.3,49.37 116.2,51.27 116.83,51.27 IN3-4.16
N$33  (via drill 0.61)
  Top 0.254: v37.46,28.41 37.46,33.49 36.19,34.76 36.19,37.3 IC3.12 | v12.06,27.14 10.79,28.41 10.79,31.58 OUT3-4.1
  Bottom 0.254: v37.46,28.41 19.68,28.41 19.04,27.77 12.7,27.77 v12.06,27.14
N$34  (via drill 0.61)
  Top 0.254: v14.6,35.39 14.6,34.76 11.43,34.76 OUT3-4.3 | v28.57,36.03 28.57,37.3 IC3.15
  Bottom 0.254: v14.6,35.39 15.24,36.03 v28.57,36.03
N$35
  Bottom 0.254: IC3.16 25.39,37.94 24.12,36.66 10.79,36.66 OUT3-4.5
N$36
  Bottom 0.254: IC3.19 17.77,39.2 16.5,40.48 10.79,40.48 OUT3-4.7
N$37
  Bottom 0.254: IC13.3 95.24,30.31 96.52,29.04 102.86,29.04 103.5,29.68 103.5,34.76 106.04,34.76 107.31,33.49 116.83,33.49 IN3-4.2
N$38
  Bottom 0.254: IC13.4 97.78,31.58 102.23,36.03 116.83,36.03 IN3-4.4
N$39  (via drill 0.61)
  Top 0.254: v116.2,29.04 115.56,29.68 115.56,37.3 116.83,38.57 IN3-4.6
  Bottom 0.254: v116.2,29.04 114.93,30.31 114.3,30.31 113.02,29.04 105.41,29.04 104.77,29.68 IC13.7
N$40  (via drill 0.61)
  Top 0.254: v108.58,40.48 108.58,33.49 107.94,32.85 107.94,31.58 IC13.8
  Bottom 0.254: v108.58,40.48 109.21,41.11 116.83,41.11 IN3-4.8
N$41  (via drill 0.61)
  Top 0.254: v106.04,45.55 106.04,51.27 106.67,51.91 IC14.13
  Bottom 0.254: v106.04,45.55 113.02,45.55 113.66,44.92 118.1,44.92 118.74,44.28 120.01,44.28 IN3-4.9
N$42  (via drill 0.61)
  Top 0.254: v126.99,62.7 v126.99,46.19 | v106.04,61.43 106.04,52.54 105.41,51.91 IC14.14
  Bottom 0.254: v126.99,46.19 120.64,46.19 IN3-4.11 | v126.99,62.7 116.83,62.7 115.56,61.43 v106.04,61.43
N$43  (via drill 0.61)
  Top 0.254: v122.55,48.73 123.19,49.37 123.19,56.98 124.45,58.25 124.45,78.58 v125.09,79.21 | v100.96,80.48 98.42,77.94 98.42,72.86 95.88,70.32 95.88,55.08 97.15,53.81 97.15,52.54 IC14.17
  Bottom 0.254: v122.55,48.73 120.64,48.73 IN3-4.13 | v125.09,79.21 123.82,80.48 121.28,80.48 120.64,79.84 107.31,79.84 106.04,81.11 101.59,81.11 v100.96,80.48
N$44
  Bottom 0.254: IC14.18 95.24,51.91 96.52,53.17 117.47,53.17 119.38,51.27 IN3-4.15
N$45  (via drill 0.61)
  Top 0.254: v107.31,34.76 107.31,37.3 IC13.13
  Bottom 0.254: v107.31,34.76 118.1,34.76 118.74,34.12 120.01,34.12 IN3-4.1
N$46  (via drill 0.61)
  Top 0.254: v104.77,33.49 104.77,37.3 IC13.14 | v118.74,32.22 118.74,34.12 119.38,34.76 120.01,34.76 120.01,35.39 IN3-4.3
  Bottom 0.254: v104.77,33.49 105.41,32.85 116.2,32.85 116.83,32.22 v118.74,32.22
N$47
  Bottom 0.254: IC13.17 97.78,37.94 99.05,36.66 116.2,36.66 116.83,37.3 118.1,37.3 119.38,38.57 IN3-4.5
N$48  (via drill 0.61)
  Top 0.254: v124.45,41.11 124.45,53.17 v125.09,53.81 | v93.34,53.17 93.34,41.11 93.97,40.48 93.97,39.2 IC13.18
  Bottom 0.254: v124.45,41.11 120.64,41.11 IN3-4.7 | v125.09,53.81 111.12,53.81 110.48,54.45 97.78,54.45 97.15,53.81 93.97,53.81 v93.34,53.17
N$49
  Bottom 0.254: IC3.5 25.39,31.58 24.12,32.85 14.6,32.85 13.97,32.22 12.7,32.22 11.43,33.49 10.16,33.49 8.89,34.76 OUT3-4.4
N$50  (via drill 0.61)
  Top 0.254: v6.34,27.77 v6.34,37.3
  Bottom 0.254: v6.34,27.77 8.25,27.77 8.89,28.41 18.41,28.41 19.04,29.04 27.93,29.04 28.57,29.68 IC3.6 | v6.34,37.3 7.62,37.3 OUT3-4.6
N$51  (via drill 0.61)
  Top 0.254: v8.25,29.04 8.25,31.58 OUT3-4.2
  Bottom 0.254: v8.25,29.04 17.77,29.04 18.41,29.68 IC3.2
N$52
  Bottom 0.254: IC3.9 35.55,31.58 33.02,34.12 14.6,34.12 12.7,36.03 6.34,36.03 3.8,38.57 3.8,39.84 7.62,39.84 OUT3-4.8
N$53
  Bottom 0.254: IC1.12 36.83,12.54 40.64,8.73 75.56,8.73 76.19,9.36 88.26,9.36 90.8,6.82 90.8,2.38 46.98,2.38 45.08,4.28 45.08,7.46 36.19,7.46 34.92,8.73 25.39,8.73 24.76,9.36 12.7,9.36 11.43,8.09 OUT1-2.1
N$54
  Bottom 0.254: IC1.15 27.93,12.54 26.03,10.63 11.43,10.63 OUT1-2.3
N$55
  Top 0.254: IC1.16 26.03,11.9 25.39,11.27 25.39,7.46 24.76,6.82 24.76,4.28 24.12,3.64 19.68,3.64 19.68,6.82 17.14,9.36 12.06,9.36 12.06,11.27 10.79,12.54 OUT1-2.5
N$56
  Bottom 0.254: IC1.19 17.77,13.81 15.87,15.71 11.43,15.71 OUT1-2.7
N$57
  Top 0.254: IC1.2 17.77,6.18 16.5,7.46 14.6,7.46 14.6,5.55 13.33,4.28 8.25,4.28 8.25,7.46 OUT1-2.2
N$58  (via drill 0.61)
  Top 0.254: v7.62,3.64 7.62,6.18 6.98,6.82 6.98,10 7.62,10.63 OUT1-2.4
  Bottom 0.254: v7.62,3.64 25.39,3.64 26.03,4.28 IC1.5
N$59  (via drill 0.61)
  Top 0.254: v28.57,10.63 28.57,6.82 IC1.6 | v19.68,15.08 19.68,11.9 17.77,10 12.7,10 12.7,11.9 12.06,12.54 v12.06,14.44
  Bottom 0.254: v28.57,10.63 29.84,11.9 29.84,15.08 v19.68,15.08 | v12.06,14.44 9.52,14.44 8.89,13.81 8.25,13.81 OUT1-2.6
N$60  (via drill 0.61)
  Top 0.254: v9.52,6.82 9.52,13.81 8.89,14.44 8.25,14.44 8.25,15.08 OUT1-2.8
  Bottom 0.254: v9.52,6.82 13.97,6.82 15.87,8.73 24.12,8.73 25.39,7.46 34.92,7.46 35.55,6.82 36.19,6.82 IC1.9
N$61
  Bottom 0.254: IC2.19 17.77,25.23 16.5,23.96 13.33,23.96 11.43,25.87 OUT1-2.15
N$62
  Bottom 0.254: IC2.16 25.39,25.23 23.49,23.33 11.43,23.33 OUT1-2.13
N$63  (via drill 0.61)
  Top 0.254: v28.57,22.06 28.57,24.6 IC2.15
  Bottom 0.254: v28.57,22.06 12.7,22.06 12.06,21.42 10.79,21.42 OUT1-2.11
N$64
  Top 0.254: IC2.12 36.83,26.5 41.91,31.58 41.91,39.2 41.27,39.84 41.27,42.38 40.64,43.02 40.64,104.61 39.37,105.88 7.62,105.88 7.62,103.34 6.98,102.7 6.98,102.07 1.27,96.36 1.27,23.33 5.08,19.52 10.79,19.52 10.79,18.88 OUT1-2.9
N$65
  Bottom 0.254: IC2.2 17.77,17.61 16.5,16.34 12.06,16.34 11.43,16.98 10.16,16.98 8.89,18.25 OUT1-2.10
N$66
  Bottom 0.254: IC2.5 26.66,17.61 27.93,16.34 29.2,16.34 29.84,16.98 29.84,23.33 24.76,23.33 24.12,22.7 12.06,22.7 11.43,22.06 10.16,22.06 8.89,20.79 OUT1-2.12
N$67
  Bottom 0.254: IC2.6 27.93,18.88 26.66,20.15 14.6,20.15 13.97,19.52 7.62,19.52 6.98,20.15 6.98,23.33 7.62,23.33 OUT1-2.14
N$68  (via drill 0.61)
  Top 0.254: v18.41,15.71 14.6,15.71 12.06,18.25 12.06,23.96 11.43,24.6 10.16,24.6 8.89,25.87 OUT1-2.16 | v36.19,15.71 36.19,16.98 IC2.9
  Bottom 0.254: v18.41,15.71 19.04,16.34 19.68,16.34 20.31,15.71 v36.19,15.71
N$69
  Bottom 0.254: IC4.2 18.41,42.38 17.14,41.11 10.16,41.11 8.89,42.38 OUT3-4.10
N$70  (via drill 0.61)
  Top 0.254: v6.34,43.65 6.98,43.02 6.98,41.74 7.62,41.11 12.7,41.11 v12.7,42.38
  Bottom 0.254: v6.34,43.65 7.62,43.65 8.25,44.28 OUT3-4.12 | v12.7,42.38 13.33,41.74 16.5,41.74 17.14,42.38 17.14,45.55 25.39,45.55 26.03,44.92 IC4.5
N$71  (via drill 0.61)
  Top 0.254: v3.17,30.31 v3.17,46.82 | v12.06,30.31 13.97,28.41 13.97,27.77 14.6,27.14 14.6,16.98 15.24,16.34 17.14,16.34 17.14,22.06 19.68,24.6 19.68,27.14 17.14,29.68 17.14,33.49 17.77,34.12 17.77,35.39 19.68,37.3 v19.68,40.48
  Bottom 0.254: v3.17,46.82 3.8,47.46 7.62,47.46 OUT3-4.14 | v12.06,30.31 v3.17,30.31 | v19.68,40.48 20.95,41.74 27.93,41.74 28.57,42.38 IC4.6
N$72  (via drill 0.61)
  Top 0.254: v36.19,48.73 36.19,44.92 IC4.9 | v6.34,46.19 5.08,47.46 v5.08,50
  Bottom 0.254: v36.19,48.73 19.68,48.73 19.04,48.09 13.33,48.09 11.43,46.19 v6.34,46.19 | v5.08,50 7.62,50 OUT3-4.16
N$73
  Bottom 0.254: IC4.19 17.77,50.63 16.5,49.37 10.79,49.37 OUT3-4.15
N$74  (via drill 0.61)
  Top 0.254: v12.06,43.65 12.06,45.55 11.43,46.19 11.43,47.46 OUT3-4.13 | v26.03,46.19 26.03,50 IC4.16
  Bottom 0.254: v12.06,43.65 13.33,44.92 13.97,44.92 15.24,46.19 v26.03,46.19
N$75  (via drill 0.61)
  Top 0.254: v9.52,48.73 9.52,45.55 10.16,44.92 OUT3-4.11
  Bottom 0.254: v9.52,48.73 18.41,48.73 19.04,49.37 27.93,49.37 28.57,50 IC4.15
N$76  (via drill 0.61)
  Top 0.254: v37.46,58.89 37.46,52.54 36.83,51.91 IC4.12 | v29.84,58.89 27.3,61.43 v27.3,100.16 | v9.52,103.34 9.52,101.44 8.89,100.8 6.98,100.8 1.9,95.72 1.9,49.37 7.62,43.65 8.89,43.65 10.16,42.38 OUT3-4.9
  Bottom 0.254: v29.84,58.89 v37.46,58.89 | v27.3,100.16 27.3,103.97 13.33,103.97 12.06,102.7 11.43,103.34 v9.52,103.34
N$77
  Bottom 0.254: IC16.3 95.24,68.41 96.52,67.14 114.93,67.14 116.83,69.05 IN5-6.10
N$78  (via drill 0.61)
  Top 0.254: v103.5,70.95 v103.5,85.56 | v111.12,85.56 v111.12,72.22
  Bottom 0.254: v103.5,70.95 97.78,70.95 97.15,70.32 IC16.4 | v103.5,85.56 v111.12,85.56 | v111.12,72.22 111.75,71.59 116.83,71.59 IN5-6.12
N$79  (via drill 0.61)
  Top 0.254: v104.77,72.86 104.77,70.32 IC16.7
  Bottom 0.254: v104.77,72.86 107.94,72.86 109.21,74.13 116.83,74.13 IN5-6.14
N$80  (via drill 0.61)
  Top 0.254: v107.94,74.13 107.94,69.69 IC16.8
  Bottom 0.254: v107.94,74.13 108.58,74.77 113.02,74.77 114.93,76.67 116.83,76.67 IN5-6.16
N$81  (via drill 0.61)
  Top 0.254: v37.46,73.5 37.46,65.24 36.83,64.61 IC5.12 | v29.84,78.58 v29.84,74.13 | v5.71,77.3 6.34,76.67 6.34,55.08 8.25,53.17 10.79,53.17 10.79,58.25 OUT5-6.1
  Bottom 0.254: v37.46,73.5 36.83,74.13 v29.84,74.13 | v29.84,78.58 10.79,78.58 10.16,77.94 6.98,77.94 6.34,77.3 v5.71,77.3
N$82
  Bottom 0.254: IC5.15 27.93,63.34 26.03,61.43 11.43,61.43 OUT5-6.3
N$83
  Bottom 0.254: IC5.16 25.39,63.34 24.12,62.06 13.33,62.06 11.43,63.97 OUT5-6.5
N$84
  Bottom 0.254: IC5.19 17.77,64.61 15.87,66.51 11.43,66.51 OUT5-6.7
N$85  (via drill 0.61)
  Top 0.254: v36.19,84.92 36.19,88.1 IC7.12
  Bottom 0.254: v36.19,84.92 35.55,84.29 23.49,84.29 22.86,83.66 14.6,83.66 13.97,83.02 11.43,83.02 10.79,83.66 OUT7-8.1
N$86
  Bottom 0.254: IC7.15 27.93,88.73 26.03,86.83 11.43,86.83 OUT7-8.3
N$87
  Bottom 0.254: IC7.16 25.39,88.73 24.12,87.47 13.33,87.47 11.43,89.37 OUT7-8.5
N$88  (via drill 0.61)
  Top 0.254: v18.41,85.56 18.41,88.1 IC7.19 | v12.06,85.56 12.06,91.28 11.43,91.91 OUT7-8.7
  Bottom 0.254: v12.06,85.56 v18.41,85.56
N$89  (via drill 0.61)
  Top 0.254: v26.03,60.16 26.03,57.62 IC5.5
  Bottom 0.254: v26.03,60.16 25.39,60.8 12.06,60.8 11.43,60.16 8.89,60.16 8.25,60.8 OUT5-6.4
N$90  (via drill 0.61)
  Top 0.254: v9.52,57.62 9.52,62.06 8.89,62.7 8.89,63.97 OUT5-6.6
  Bottom 0.254: v9.52,57.62 11.43,57.62 12.06,58.25 12.06,59.52 12.7,60.16 20.31,60.16 22.22,58.25 27.93,58.25 28.57,57.62 IC5.6
N$91  (via drill 0.61)
  Top 0.254: v45.08,54.45 44.45,53.81 44.45,47.46 v45.08,46.82 | v19.68,47.46 19.68,52.54 17.14,55.08 v17.14,58.25
  Bottom 0.254: v45.08,54.45 36.83,54.45 36.19,55.08 IC5.9 | v45.08,46.82 26.66,46.82 26.03,47.46 v19.68,47.46 | v17.14,58.25 14.6,58.25 13.97,57.62 12.7,57.62 12.06,56.98 10.16,56.98 9.52,56.35 8.89,56.35 6.34,58.89 6.34,66.51 7.62,66.51 OUT5-6.8
N$92  (via drill 0.61)
  Top 0.254: v36.19,72.22 36.19,75.4 IC6.12 | v38.73,72.22 40,73.5 40,103.97 v39.37,104.61 | v10.79,82.39 10.79,78.58 9.52,77.3 9.52,76.03 10.16,75.4 11.43,75.4 12.06,74.77 12.06,69.69 11.43,69.05 OUT5-6.9
  Bottom 0.254: v38.73,72.22 v36.19,72.22 | v39.37,104.61 39.37,105.25 8.89,105.25 7.62,103.97 7.62,103.34 6.98,102.7 6.98,102.07 1.27,96.36 1.27,82.39 v10.79,82.39
N$93
  Bottom 0.254: IC6.15 28.57,75.4 26.03,72.86 12.7,72.86 11.43,71.59 OUT5-6.11
N$94  (via drill 0.61)
  Top 0.254: v78.73,83.02 77.46,84.29 77.46,86.19 IC24.12 | v81.27,83.02 81.91,82.39 81.91,55.08 v81.27,54.45 | v57.78,54.45 57.15,53.81 57.15,51.91 56.51,51.27 56.51,50 IC26.4
  Bottom 0.254: v81.27,83.02 v78.73,83.02 | v81.27,54.45 80.64,53.81 69.21,53.81 67.94,55.08 67.3,54.45 65.4,54.45 64.77,53.81 61.59,53.81 60.96,54.45 v57.78,54.45
N$95
  Bottom 0.254: IC6.16 25.39,76.03 24.12,74.77 17.77,74.77 17.14,74.13 11.43,74.13 OUT5-6.13
N$96
  Bottom 0.254: IC6.19 17.77,76.03 16.5,74.77 13.33,74.77 11.43,76.67 OUT5-6.15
